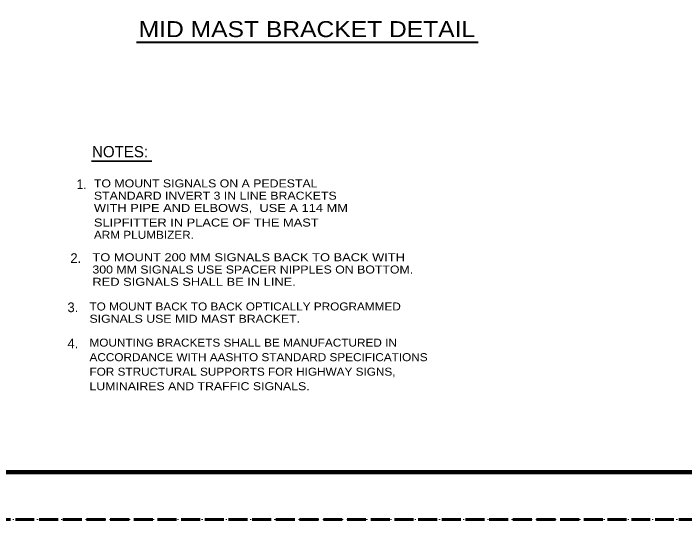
# Model space of a CAD drawing. Extents: x 312583 to 312854, y 144419 to 144597.
# Drawn here: x 312647.3 to 312711, y 144418.6 to 144466.7 of the extents above; entities that cross this region are included whole.
import ezdxf
from ezdxf.enums import TextEntityAlignment as Align

# ---------------------------------------------------------------- set-up
doc = ezdxf.new("R2010")
doc.units = 0
doc.header["$LTSCALE"] = 0.3
doc.linetypes.add('DOTTED', pattern=[1.5, 0.3, -1.2])
doc.linetypes.add('LONG_DASHED', pattern=[7.5, 6, -1.5])
for name, color, linetype, lineweight in [('1', 7, 'Continuous', 40), ('2', 7, 'Continuous', 40), ('62', 7, 'DOTTED', 13), ('63', 7, 'LONG_DASHED', 60)]:
    doc.layers.add(name, color=color, linetype=linetype, lineweight=lineweight)

msp = doc.modelspace()

# ---------------------------------------------------------------- linework, layer by layer
at = {"layer": '1', "lineweight": 158}
msp.add_line((312616.5, 144423.0846), (312849, 144423.0846), dxfattribs=at)
at = {"layer": '2'}
msp.add_line((312658.9624, 144463.9603), (312691.4014, 144463.9603), dxfattribs=at)
at = {"layer": '2', "lineweight": 35}
msp.add_line((312654.6812, 144452.6554), (312660.4005, 144452.6554), dxfattribs=at)
at = {"layer": '62'}
msp.add_lwpolyline([(312601.2, 144418.5846), (312853.5, 144418.5846), (312853.5, 144596.7846)], dxfattribs=at)
at = {"layer": '63'}
msp.add_line((312851.75, 144418.5846), (312583.526, 144418.5846), dxfattribs=at)

# ---------------------------------------------------------------- texts
at = {"layer": '2', "width": 1.15}
msp.add_text('MID MAST BRACKET DETAIL', height=1.52, dxfattribs=at).set_placement((312675.1394, 144464.4327), align=Align.CENTER)
at = {"layer": '2'}
msp.add_text('NOTES:', height=1.07, dxfattribs=at).set_placement((312657.3949, 144453.0136), align=Align.CENTER)
at = {"layer": '2', "width": 0.9}
msp.add_text('1.', height=0.92, dxfattribs=at).set_placement((312654.1961, 144449.9917), align=Align.RIGHT)
at = {"layer": '2'}
for s, width, p in [('TO MOUNT SIGNALS ON A PEDESTAL', 1.15, (312654.9091, 144450.1517)), ('STANDARD INVERT 3 IN LINE BRACKETS', 1.15, (312654.9091, 144448.9854)), ('WITH PIPE AND ELBOWS,  USE A 114 MM', 1.2, (312654.9091, 144447.8191)), ('SLIPFITTER IN PLACE OF THE MAST', 1.2, (312654.9091, 144446.4326)), ('ARM PLUMBIZER.', 1.1, (312654.9091, 144445.2663)), ('TO MOUNT 200 MM SIGNALS BACK TO BACK WITH', 1.2, (312654.7689, 144443.1347)), ('300 MM SIGNALS USE SPACER NIPPLES ON BOTTOM.', 1.15, (312654.7689, 144441.9684)), ('RED SIGNALS SHALL BE IN LINE.', 1.2, (312654.7689, 144440.8021)), ('TO MOUNT BACK TO BACK OPTICALLY PROGRAMMED', 1.1, (312654.4887, 144438.4566)), ('SIGNALS USE MID MAST BRACKET.', 1.15, (312654.4887, 144437.2903)), ('MOUNTING BRACKETS SHALL BE MANUFACTURED IN', 1.1, (312654.4887, 144435.0183)), ('ACCORDANCE WITH AASHTO STANDARD SPECIFICATIONS', 1.1, (312654.4887, 144433.6383)), ('FOR STRUCTURAL SUPPORTS FOR HIGHWAY SIGNS,', 1.1, (312654.4887, 144432.2583)), ('LUMINAIRES AND TRAFFIC SIGNALS.', 1.15, (312654.4887, 144430.8783))]:
    msp.add_text(s, height=0.76, dxfattribs=dict(at, width=width)).set_placement(p)
for s, p in [('2.', (312653.7031, 144442.9747)), ('3.', (312653.4229, 144438.2966)), ('4.', (312653.4229, 144434.8583))]:
    msp.add_text(s, height=0.92, dxfattribs=at).set_placement(p, align=Align.RIGHT)

doc.saveas('drawing.dxf')
